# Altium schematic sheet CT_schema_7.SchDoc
size 403 x 220 mm
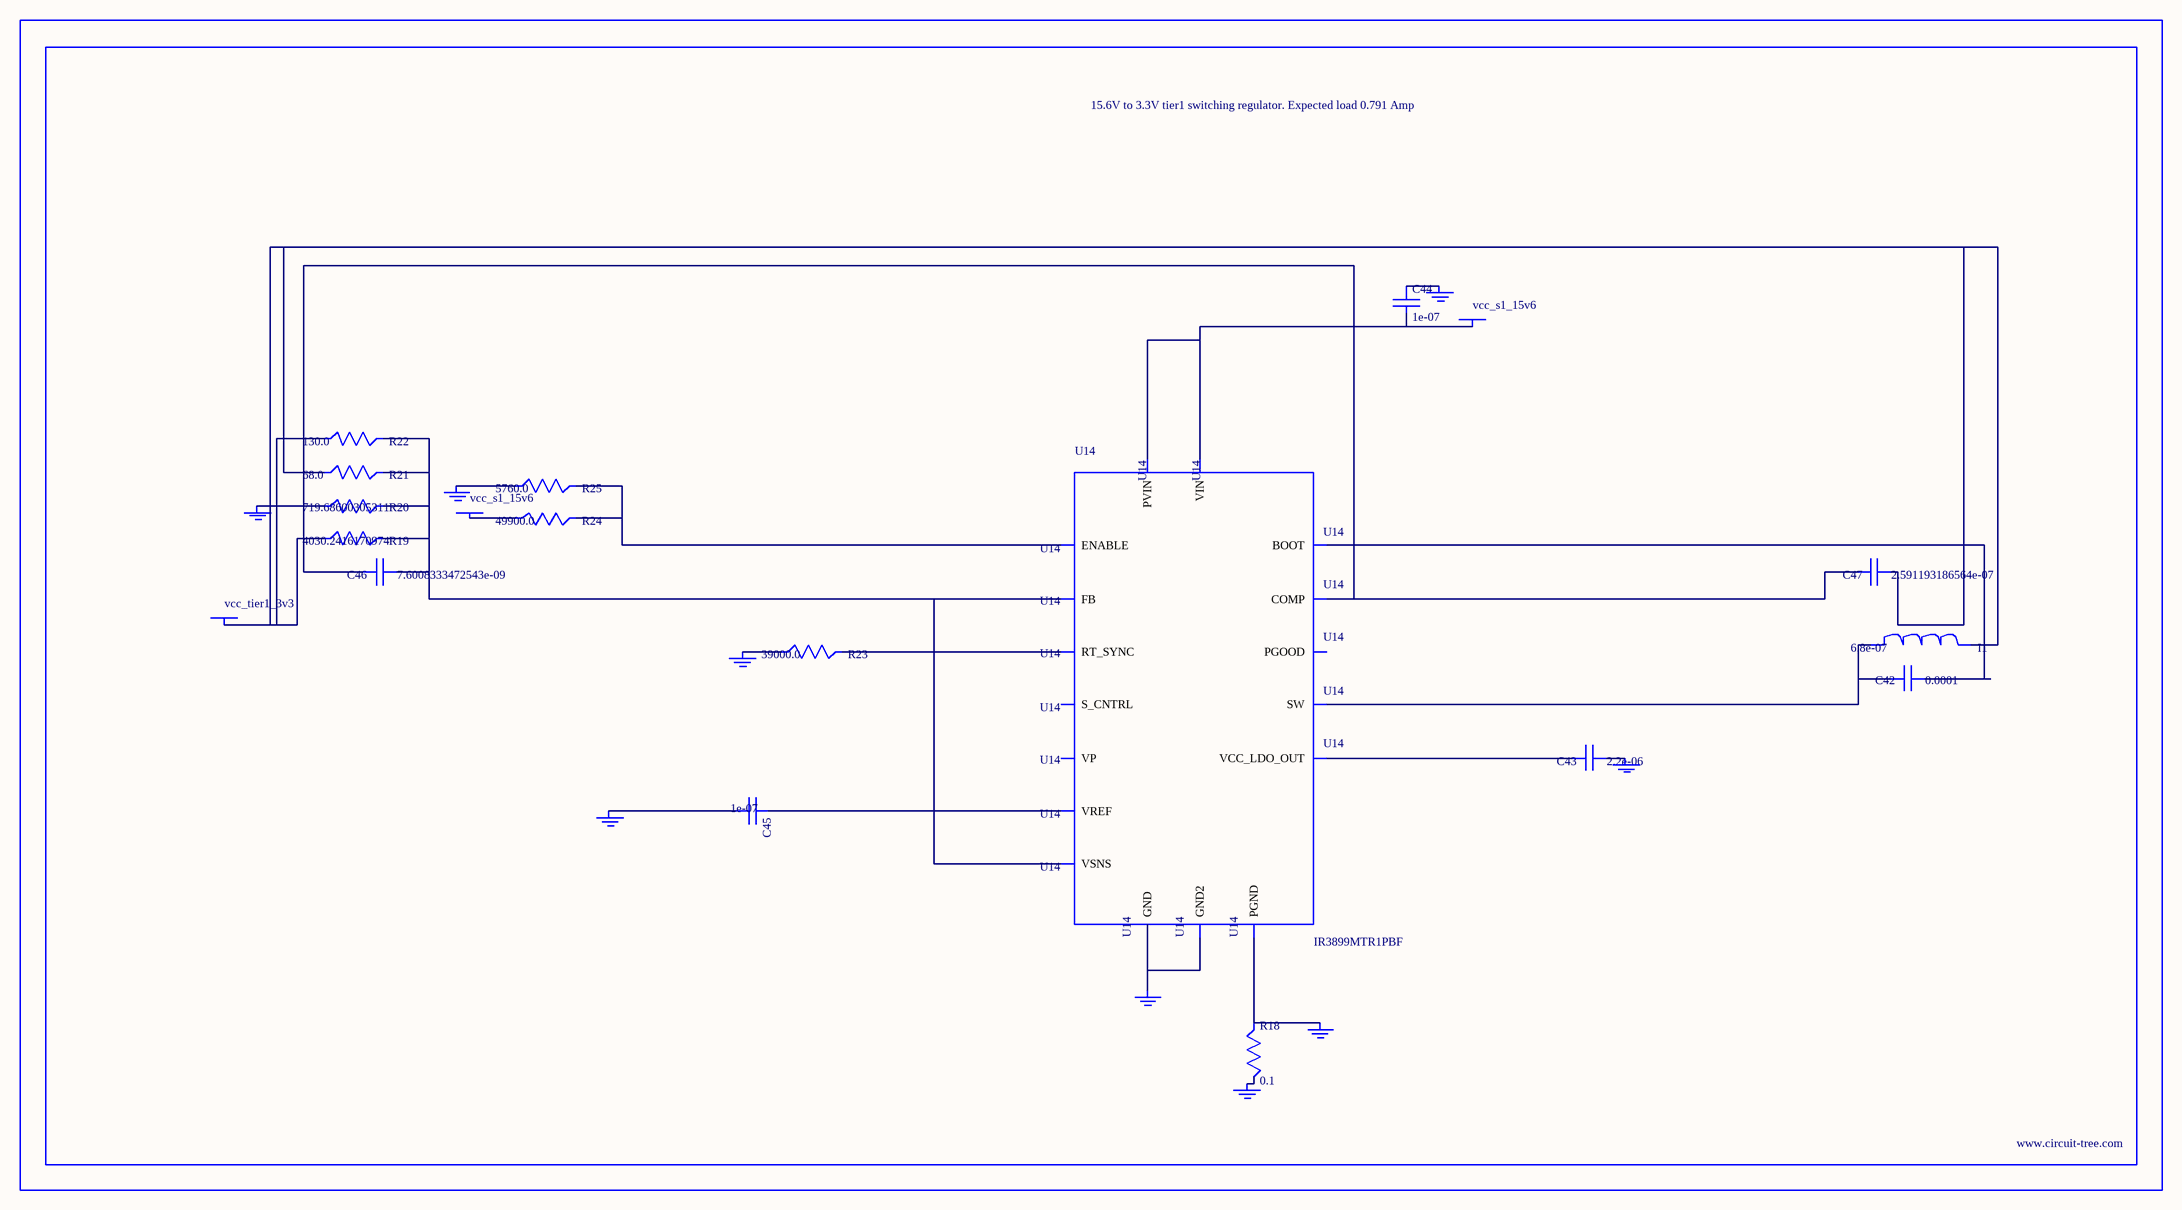
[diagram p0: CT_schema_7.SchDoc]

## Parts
BORDER6  (no value)
C42  0.0001  [C1210]
C43  2.2e-06  [C0603]
C44  1e-07  [C0402]
C45  1e-07  [C0402]
C46  7.6008333472543e-09  [R0603]
C47  2.591193186564e-07  [R0603]
GND_INSTANCE_6_0  (no value)
GND_INSTANCE_6_1  (no value)
GND_INSTANCE_6_2  (no value)
GND_INSTANCE_6_3  (no value)
GND_INSTANCE_6_4  (no value)
GND_INSTANCE_6_5  (no value)
GND_INSTANCE_6_6  (no value)
GND_INSTANCE_6_7  (no value)
GND_INSTANCE_6_8  (no value)
I1  6.8e-07  [IND25X25CZ]
POWER_INSTANCE_6_0  vcc_s1_15v6
POWER_INSTANCE_6_1  vcc_s1_15v6
POWER_INSTANCE_6_2  vcc_tier1_3v3
R18  0.1  [R0603]
R19  4030.2416170974  [R0603]
R20  719.68600305311  [R0603]
R21  68.0  [R0603]
R22  130.0  [R0603]
R23  39000.0  [R0603]
R24  49900.0  [R0603]
R25  5760.0  [R0603]
U14  IR3899MTR1PBF  [IR3899MTR1PBF]

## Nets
NetC42_1: C42.1 U14.14(BOOT)
NetC42_2: C42.2 I1.1 U14.12(SW)
NetC43_1: C43.1 GND_INSTANCE_6_4.0(GND)
NetC43_2: C43.2 U14.10(VCC_LDO_OUT)
NetC44_1: C44.1 GND_INSTANCE_6_3.0(GND)
NetC44_2: C44.2 POWER_INSTANCE_6_0.0(PWR) U14.9(VIN) U14.13(PVIN)
NetC45_1: C45.1 U14.2(VREF)
NetC45_2: C45.2 GND_INSTANCE_6_1.0(GND)
NetC46_1: C46.1 R19.2 R20.2 R21.2 R22.2 U14.1(FB) U14.8(VSNS)
NetC46_2: C46.2 C47.2 U14.3(COMP)
NetC47_1: C47.1 I1.2 POWER_INSTANCE_6_2.0(PWR) R19.1 R21.1 R22.1
NetGND_INSTANCE_6_0_0: GND_INSTANCE_6_0.0(GND) R20.1
NetGND_INSTANCE_6_2_0: GND_INSTANCE_6_2.0(GND) R23.1
NetGND_INSTANCE_6_5_0: GND_INSTANCE_6_5.0(GND) R18.2
NetGND_INSTANCE_6_6_0: GND_INSTANCE_6_6.0(GND) R18.1 U14.11(PGND)
NetGND_INSTANCE_6_7_0: GND_INSTANCE_6_7.0(GND) R25.1
NetGND_INSTANCE_6_8_0: GND_INSTANCE_6_8.0(GND) U14.4(GND) U14.17(GND2)
NetPOWER_INSTANCE_6_1_0: POWER_INSTANCE_6_1.0(PWR) R24.1
NetR23_2: R23.2 U14.5(RT_SYNC)
NetR24_2: R24.2 R25.2 U14.15(ENABLE)

Not connected (* = marked no-connect by the designer): U14 6(S_CNTRL) 7(PGOOD) 16(VP)

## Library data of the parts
BORDER6 = BORDER_PAGE6
C42 = GRM32ER61A107ME20L
C43 = C0603C225K8RACTU
C44 C45 = C0402C104K3RACTU
C46 = C46
C47 = C47
GND_INSTANCE_6_0-GND_INSTANCE_6_8 = GND
I1 = IHLP2525CZERR68M01
POWER_INSTANCE_6_0-POWER_INSTANCE_6_2 = PWR
R18 = ERJ-3RSFR10V
R19 = R19
R20 = R20
R21 = RC0603JR-0768RL
R22 = RC0603JR-07130RL
R23 = RC0603JR-0739KL
R24 = RC0603FR-0749K9
R25 = ERJ-3EKF5760V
